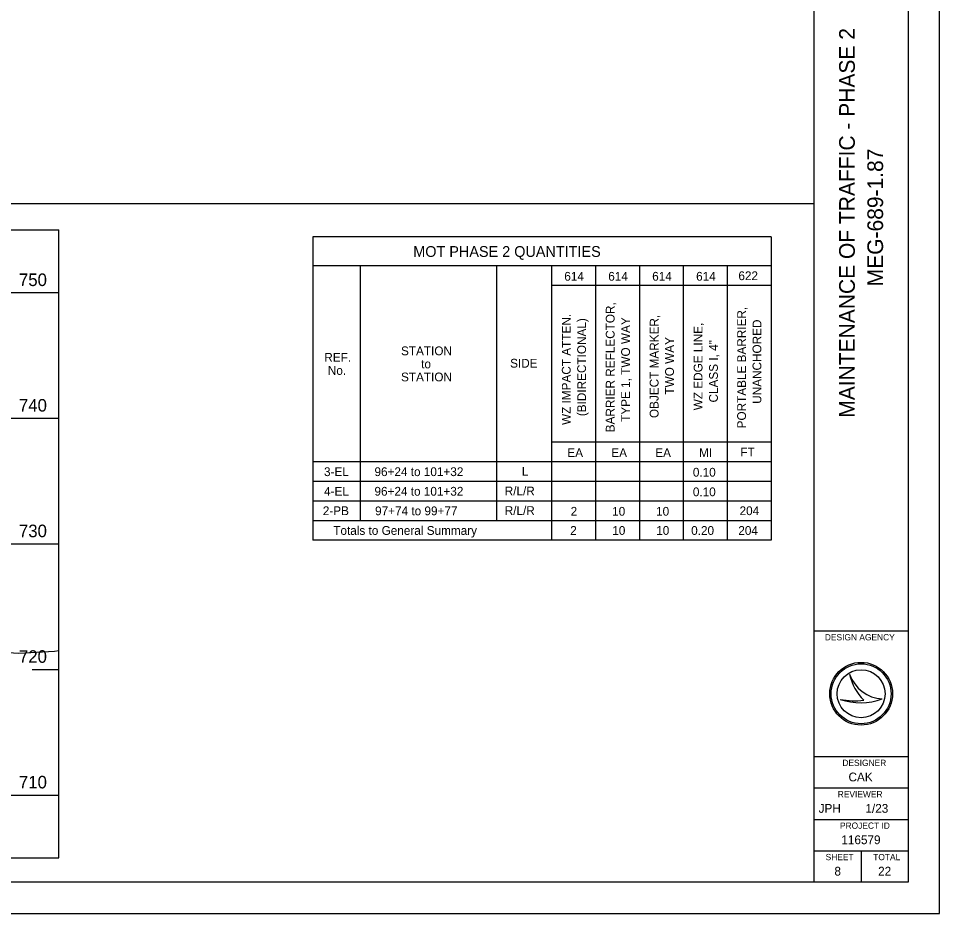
# Model space of a CAD drawing. Extents: x -8.7 to 76.9, y -12.1 to 38.2.
# Drawn here: x 19.33 to 34, y 0 to 14.25 of the extents above; entities that cross this region are included whole.
import ezdxf

# ---------------------------------------------------------------- set-up
doc = ezdxf.new("R2010")
doc.units = 0
for name, color, linetype in [('DR_P_Drive_Pipe', 7, 'Continuous'), ('SH_Border', 7, 'Continuous'), ('SH_Cut_Line', 7, 'Continuous'), ('SH_Data', 7, 'Continuous'), ('SH_Major_Grid_Line', 7, 'Continuous'), ('SH_Text', 7, 'Continuous'), ('XS_X_Ground_Line', 7, 'Continuous')]:
    doc.layers.add(name, color=color, linetype=linetype)

msp = doc.modelspace()

# ---------------------------------------------------------------- linework, layer by layer
at = {"layer": 'DR_P_Drive_Pipe'}
msp.add_line((1.5, 11.307), (32, 11.307), dxfattribs=at)
at = {"layer": 'SH_Border'}
for p, q in [((32, 0.5), (32, 21.5)), ((32, 4.5), (33.5, 4.5)), ((32, 2.5), (33.5, 2.5)), ((32, 2), (33.5, 2)), ((32, 1.5), (33.5, 1.5)), ((32, 1), (33.5, 1)), ((32.75, 1), (32.75, 0.5))]:
    msp.add_line(p, q, dxfattribs=at)
msp.add_lwpolyline([(1.5, 21.5), (33.5, 21.5), (33.5, 0.5), (1.5, 0.5)], close=True, dxfattribs=at)
at = {"layer": 'SH_Cut_Line'}
msp.add_lwpolyline([(0, 0), (34, 0), (34, 22), (0, 22)], close=True, dxfattribs=at)
at = {"layer": 'SH_Data'}
for p, q in [((24.018, 10.774), (24.018, 5.944)), ((31.318, 10.774), (24.018, 10.774)), ((31.318, 10.774), (31.318, 5.944)), ((31.318, 10.312), (24.018, 10.312)), ((24.768, 10.312), (24.768, 6.256)), ((26.943, 10.312), (26.943, 6.256)), ((27.818, 10.312), (27.818, 5.944)), ((28.518, 10.312), (28.518, 5.944)), ((29.218, 10.312), (29.218, 5.944)), ((29.918, 10.312), (29.918, 5.944)), ((30.618, 10.312), (30.618, 5.944)), ((31.318, 10), (27.818, 10)), ((31.318, 7.504), (27.818, 7.504)), ((31.318, 7.192), (24.018, 7.192)), ((31.318, 6.88), (24.018, 6.88)), ((31.318, 6.568), (24.018, 6.568)), ((31.318, 6.256), (24.018, 6.256)), ((31.318, 5.944), (24.018, 5.944)), ((32.567, 3.81), (32.567, 3.81)), ((32.417, 3.41), (32.417, 3.41)), ((32.75, 3.5), (32.75, 3.5)), ((33.087, 3.419), (33.087, 3.419))]:
    msp.add_line(p, q, dxfattribs=at)
for radius in [0.5, 0.477, 0.477, 0.382]:
    msp.add_circle((32.75, 3.5), radius, dxfattribs=at)
for centre, radius, start, end in [((33.116, 3.998), 0.58, 198.9257, 198.9319), ((33.347, 3.97), 0.796, 191.6379, 191.6421), ((33.116, 3.998), 0.58, 198.9319, 267.1657), ((33.347, 3.97), 0.796, 191.6421, 226.0947), ((32.739, 4.37), 1.013, 251.4576, 290.0832), ((32.648, 4.654), 1.266, 259.4964, 259.4995), ((32.739, 4.37), 1.013, 251.4527, 251.4576), ((32.648, 4.654), 1.266, 259.4995, 276.6672)]:
    msp.add_arc(centre, radius, start, end, dxfattribs=at)
at = {"layer": 'SH_Major_Grid_Line'}
for p, q in [((10.97, 10.887), (19.97, 10.887)), ((19.97, 0.887), (19.97, 10.887)), ((14.575, 9.887), (19.97, 9.887)), ((16.322, 7.887), (19.97, 7.887)), ((17.594, 5.887), (19.97, 5.887)), ((19.546, 3.887), (19.97, 3.887)), ((10.97, 1.887), (19.97, 1.887)), ((10.97, 0.887), (19.97, 0.887))]:
    msp.add_line(p, q, dxfattribs=at)
at = {"layer": 'XS_X_Ground_Line'}
msp.add_lwpolyline([(18.827, 4.177), (19.331, 4.149), (19.902, 4.178), (19.97, 4.191)], dxfattribs=at)

# ---------------------------------------------------------------- texts
at = {"layer": 'SH_Data'}
msp.add_text('MOT PHASE 2 QUANTITIES', height=0.17175, rotation=360, dxfattribs=at).set_placement((25.616, 10.456))
for s, p in [('DESIGN AGENCY', (32.172, 4.35)), ('DESIGNER', (32.452, 2.35)), ('REVIEWER', (32.378, 1.85)), ('PROJECT ID', (32.413, 1.35)), ('SHEET', (32.185, 0.85)), ('TOTAL', (32.943, 0.85))]:
    msp.add_text(s, height=0.1, dxfattribs=at).set_placement(p)
at = {"layer": 'SH_Text'}
for s, height, rotation, p in [('MAINTENANCE OF TRAFFIC - PHASE 2', 0.25, 90, (32.65, 7.896)), ('MEG-689-1.87', 0.25, 90, (33.1, 9.988)), ('614', 0.14, 360, (28.022, 10.077)), ('614', 0.14, 360, (28.722, 10.077)), ('614', 0.14, 360, (29.422, 10.077)), ('614', 0.14, 360, (30.122, 10.077)), ('622', 0.14, 360, (30.795, 10.086)), ('BARRIER REFLECTOR,', 0.14, 90, (28.823, 7.664)), ('PORTABLE BARRIER,', 0.14, 90, (30.916, 7.726)), ('WZ IMPACT ATTEN.', 0.14, 90, (28.123, 7.78)), ('(BIDIRECTIONAL)', 0.14, 90, (28.368, 7.92)), ('TYPE 1, TWO WAY', 0.14, 90, (29.068, 7.83)), ('OBJECT MARKER,', 0.14, 90, (29.523, 7.89)), ('UNANCHORED', 0.14, 90, (31.161, 8.117)), ('WZ EDGE LINE,', 0.14, 90, (30.223, 8.014)), ('TWO WAY', 0.14, 90, (29.768, 8.264)), ('CLASS I, 4"', 0.14, 90, (30.468, 8.138)), ('STATION', 0.14, 360, (25.421, 8.89)), ('REF.', 0.14, 360, (24.199, 8.786)), ('to', 0.14, 360, (25.742, 8.682)), ('SIDE', 0.14, 360, (27.159, 8.693)), ('No.', 0.14, 360, (24.255, 8.578)), ('STATION', 0.14, 360, (25.421, 8.474)), ('EA', 0.14, 360, (28.071, 7.269)), ('EA', 0.14, 360, (28.771, 7.269)), ('EA', 0.14, 360, (29.471, 7.269)), ('MI', 0.14, 360, (30.168, 7.269)), ('FT', 0.14, 360, (30.827, 7.278)), ('3-EL', 0.14, 360, (24.194, 6.966)), ('96+24 to 101+32', 0.14, 360, (24.998, 6.966)), ('L', 0.14, 360, (27.345, 6.971)), ('0.10', 0.14, 360, (30.07, 6.957)), ('4-EL', 0.14, 360, (24.195, 6.654)), ('96+24 to 101+32', 0.14, 360, (24.998, 6.654)), ('R/L/R', 0.14, 360, (27.073, 6.659)), ('0.10', 0.14, 360, (30.07, 6.645)), ('2-PB', 0.14, 360, (24.175, 6.344)), ('97+74 to 99+77', 0.14, 360, (25.008, 6.342)), ('R/L/R', 0.14, 360, (27.073, 6.347)), ('2', 0.14, 360, (28.123, 6.335)), ('10', 0.14, 360, (28.784, 6.335)), ('10', 0.14, 360, (29.484, 6.335)), ('204', 0.14, 360, (30.814, 6.344)), ('Totals to General Summary', 0.14, 360, (24.342, 6.03)), ('2', 0.14, 360, (28.116, 6.03)), ('10', 0.14, 360, (28.786, 6.03)), ('10', 0.14, 360, (29.486, 6.03)), ('0.20', 0.14, 360, (30.043, 6.03)), ('204', 0.14, 360, (30.794, 6.03)), ('CAK', 0.14, 360, (32.549, 2.105)), ('JPH', 0.14, 360, (32.073, 1.605)), ('1/23', 0.14, 360, (32.819, 1.605)), ('116579', 0.14, 360, (32.435, 1.105)), ('8', 0.14, 360, (32.325, 0.605)), ('22', 0.14, 360, (33.021, 0.605))]:
    msp.add_text(s, height=height, rotation=rotation, dxfattribs=at).set_placement(p)
for s, p in [('750', (19.334, 9.992)), ('740', (19.334, 7.993)), ('730', (19.334, 5.993)), ('720', (19.334, 3.993)), ('710', (19.334, 1.993))]:
    msp.add_text(s, height=0.2, dxfattribs=at).set_placement(p)

doc.saveas('drawing.dxf')
